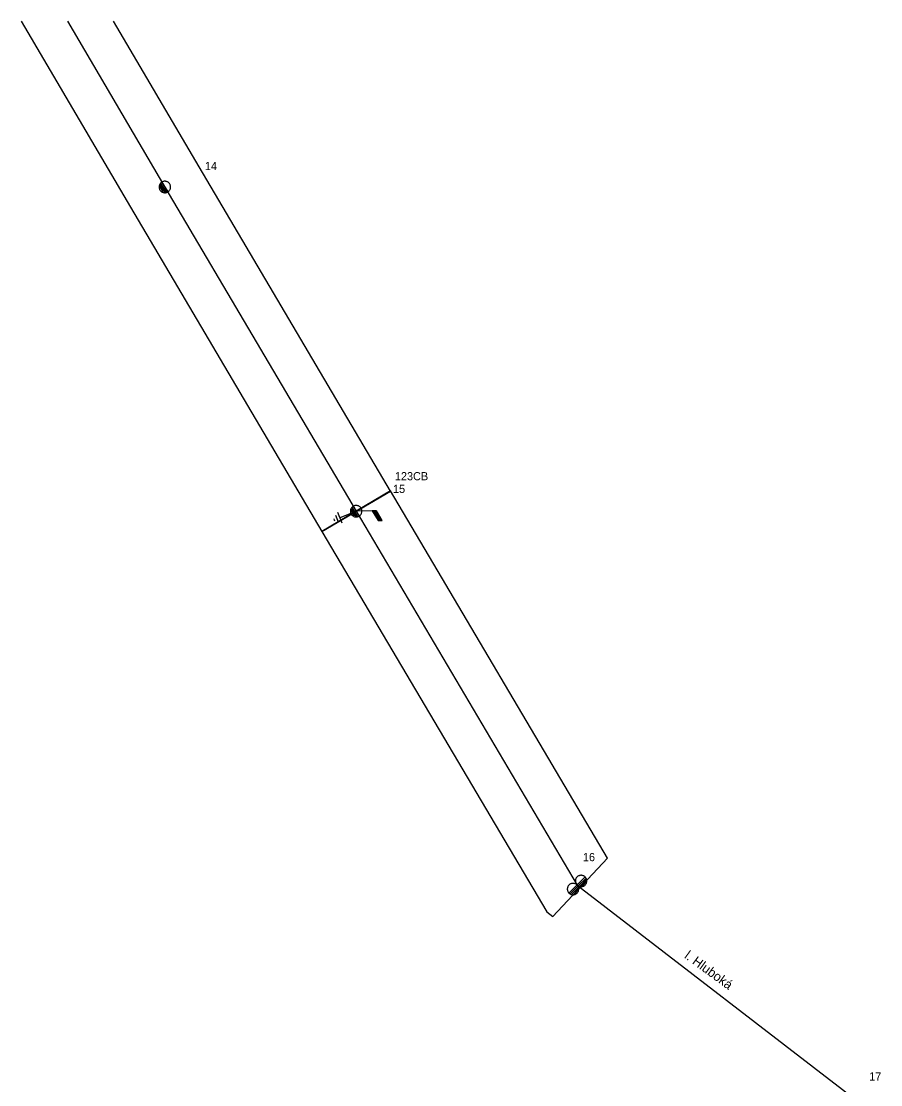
# Model space of a CAD drawing. Extents: x -762500 to -761250, y -1155000 to -1154000.
# Drawn here: x -761851.8 to -761668.3, y -1154227 to -1154000 of the extents above; entities that cross this region are included whole.
import ezdxf

# ---------------------------------------------------------------- set-up
doc = ezdxf.new("R2010")
doc.units = 0
for name, color, linetype in [('Vrstva 1', 7, 'Continuous'), ('Vrstva 11', 7, 'Continuous'), ('Vrstva 12', 7, 'Continuous'), ('Vrstva 13', 7, 'Continuous'), ('Vrstva 14', 7, 'Continuous'), ('Vrstva 15', 7, 'Continuous'), ('Vrstva 3', 7, 'Continuous'), ('Vrstva 35', 7, 'Continuous')]:
    doc.layers.add(name, color=color, linetype=linetype)

msp = doc.modelspace()

# ---------------------------------------------------------------- linework, layer by layer
at = {"layer": 'Vrstva 1'}
for points in [[(-761841.93, -1154000), (-761821.12, -1154035.38), (-761780.27, -1154104.58)], [(-761780.27, -1154104.58), (-761733.11, -1154184.36), (-761670.23, -1154232.75)]]:
    msp.add_lwpolyline(points, dxfattribs=at)
at = {"layer": 'Vrstva 11'}
for p, q in [((-761776.78, -1154104.503), (-761775.538, -1154106.571)), ((-761776.723, -1154104.502), (-761775.48, -1154106.57)), ((-761776.665, -1154104.501), (-761775.422, -1154106.569)), ((-761776.607, -1154104.499), (-761775.365, -1154106.568)), ((-761776.55, -1154104.498), (-761775.307, -1154106.567)), ((-761776.492, -1154104.497), (-761775.249, -1154106.566)), ((-761776.435, -1154104.495), (-761775.192, -1154106.565)), ((-761776.377, -1154104.494), (-761775.134, -1154106.563)), ((-761776.32, -1154104.493), (-761775.076, -1154106.562)), ((-761776.262, -1154104.492), (-761775.018, -1154106.561)), ((-761776.204, -1154104.49), (-761774.961, -1154106.56)), ((-761776.147, -1154104.489), (-761774.903, -1154106.559)), ((-761776.089, -1154104.488), (-761774.845, -1154106.558)), ((-761776.032, -1154104.487), (-761774.787, -1154106.557)), ((-761775.974, -1154104.485), (-761775.762, -1154104.838))]:
    msp.add_line(p, q, dxfattribs=at)
msp.add_lwpolyline([(-761775.973, -1154104.485), (-761780.27, -1154104.58)], dxfattribs=at)
msp.add_lwpolyline([(-761774.734, -1154106.556), (-761775.973, -1154104.485), (-761776.834, -1154104.504), (-761775.591, -1154106.572)], close=True, dxfattribs=at)
at = {"layer": 'Vrstva 13'}
for points in [[(-761820.495, -1154036.427), (-761820.388, -1154036.355), (-761820.29, -1154036.272), (-761820.201, -1154036.18), (-761820.121, -1154036.078), (-761820.053, -1154035.97), (-761819.997, -1154035.854), (-761819.953, -1154035.733), (-761819.922, -1154035.609), (-761819.904, -1154035.481), (-761819.899, -1154035.352), (-761819.908, -1154035.224), (-761819.931, -1154035.098), (-761819.966, -1154034.974), (-761820.014, -1154034.855), (-761820.075, -1154034.741), (-761820.146, -1154034.635), (-761820.229, -1154034.536), (-761820.322, -1154034.447), (-761820.423, -1154034.368), (-761820.532, -1154034.299), (-761820.648, -1154034.243), (-761820.769, -1154034.199), (-761820.894, -1154034.168), (-761821.021, -1154034.15), (-761821.149, -1154034.146), (-761821.277, -1154034.155), (-761821.404, -1154034.177), (-761821.528, -1154034.212), (-761821.647, -1154034.26), (-761821.76, -1154034.321), (-761821.867, -1154034.393), (-761821.965, -1154034.475), (-761822.055, -1154034.568), (-761822.134, -1154034.67), (-761822.202, -1154034.779), (-761822.258, -1154034.894), (-761822.302, -1154035.015), (-761822.334, -1154035.14), (-761822.351, -1154035.267), (-761822.356, -1154035.395), (-761822.347, -1154035.524), (-761822.325, -1154035.65), (-761822.289, -1154035.774), (-761822.241, -1154035.893), (-761822.181, -1154036.006), (-761822.109, -1154036.113), (-761822.026, -1154036.211), (-761821.934, -1154036.301), (-761821.832, -1154036.38), (-761821.724, -1154036.448), (-761821.608, -1154036.505), (-761821.487, -1154036.549), (-761821.362, -1154036.58), (-761821.235, -1154036.597), (-761821.106, -1154036.602), (-761820.978, -1154036.593), (-761820.852, -1154036.571), (-761820.728, -1154036.535), (-761820.609, -1154036.487), (-761820.495, -1154036.427)], [(-761822.18, -1154034.837), (-761821.162, -1154036.532)], [(-761822.022, -1154034.541), (-761820.845, -1154036.499)], [(-761821.756, -1154034.314), (-761820.49, -1154036.42)], [(-761822.288, -1154035.216), (-761821.557, -1154036.433)], [(-761779.645, -1154105.627), (-761779.538, -1154105.555), (-761779.44, -1154105.472), (-761779.351, -1154105.38), (-761779.271, -1154105.278), (-761779.203, -1154105.17), (-761779.147, -1154105.054), (-761779.103, -1154104.933), (-761779.072, -1154104.809), (-761779.054, -1154104.681), (-761779.049, -1154104.552), (-761779.058, -1154104.424), (-761779.081, -1154104.298), (-761779.116, -1154104.174), (-761779.164, -1154104.055), (-761779.225, -1154103.941), (-761779.296, -1154103.835), (-761779.379, -1154103.736), (-761779.472, -1154103.647), (-761779.573, -1154103.568), (-761779.682, -1154103.499), (-761779.798, -1154103.443), (-761779.919, -1154103.399), (-761780.044, -1154103.368), (-761780.171, -1154103.35), (-761780.299, -1154103.346), (-761780.427, -1154103.355), (-761780.554, -1154103.377), (-761780.678, -1154103.412), (-761780.797, -1154103.46), (-761780.91, -1154103.521), (-761781.017, -1154103.593), (-761781.115, -1154103.675), (-761781.205, -1154103.768), (-761781.284, -1154103.87), (-761781.352, -1154103.979), (-761781.408, -1154104.094), (-761781.452, -1154104.215), (-761781.484, -1154104.34), (-761781.501, -1154104.467), (-761781.506, -1154104.595), (-761781.497, -1154104.724), (-761781.475, -1154104.85), (-761781.439, -1154104.974), (-761781.391, -1154105.093), (-761781.331, -1154105.206), (-761781.259, -1154105.313), (-761781.176, -1154105.411), (-761781.084, -1154105.501), (-761780.982, -1154105.58), (-761780.874, -1154105.648), (-761780.758, -1154105.705), (-761780.637, -1154105.749), (-761780.512, -1154105.78), (-761780.385, -1154105.797), (-761780.256, -1154105.802), (-761780.128, -1154105.793), (-761780.002, -1154105.771), (-761779.878, -1154105.735), (-761779.759, -1154105.687), (-761779.645, -1154105.627)], [(-761781.438, -1154104.416), (-761780.707, -1154105.633)], [(-761781.33, -1154104.037), (-761780.312, -1154105.732)], [(-761781.172, -1154103.741), (-761779.995, -1154105.699)], [(-761780.906, -1154103.514), (-761779.64, -1154105.62)], [(-761731.386, -1154182.636), (-761731.481, -1154182.551), (-761731.584, -1154182.476), (-761731.694, -1154182.412), (-761731.811, -1154182.361), (-761731.932, -1154182.321), (-761732.057, -1154182.294), (-761732.184, -1154182.281), (-761732.311, -1154182.281), (-761732.438, -1154182.294), (-761732.563, -1154182.321), (-761732.684, -1154182.361), (-761732.801, -1154182.412), (-761732.912, -1154182.476), (-761733.014, -1154182.551), (-761733.109, -1154182.637), (-761733.195, -1154182.731), (-761733.27, -1154182.834), (-761733.333, -1154182.945), (-761733.385, -1154183.062), (-761733.425, -1154183.183), (-761733.451, -1154183.307), (-761733.465, -1154183.434), (-761733.465, -1154183.561), (-761733.451, -1154183.689), (-761733.425, -1154183.814), (-761733.385, -1154183.935), (-761733.333, -1154184.051), (-761733.27, -1154184.162), (-761733.195, -1154184.265), (-761733.109, -1154184.36), (-761733.014, -1154184.445), (-761732.912, -1154184.52), (-761732.801, -1154184.584), (-761732.684, -1154184.636), (-761732.563, -1154184.675), (-761732.438, -1154184.701), (-761732.311, -1154184.715), (-761732.184, -1154184.715), (-761732.057, -1154184.701), (-761731.932, -1154184.675), (-761731.811, -1154184.635), (-761731.694, -1154184.584), (-761731.584, -1154184.52), (-761731.481, -1154184.445), (-761731.386, -1154184.359), (-761731.3, -1154184.265), (-761731.226, -1154184.162), (-761731.162, -1154184.051), (-761731.11, -1154183.934), (-761731.07, -1154183.813), (-761731.044, -1154183.689), (-761731.031, -1154183.561), (-761731.031, -1154183.434), (-761731.044, -1154183.307), (-761731.071, -1154183.182), (-761731.11, -1154183.061), (-761731.162, -1154182.945), (-761731.226, -1154182.834), (-761731.3, -1154182.731), (-761731.385, -1154182.636)], [(-761733.109, -1154184.359), (-761733.205, -1154184.274), (-761733.307, -1154184.199), (-761733.418, -1154184.136), (-761733.534, -1154184.084), (-761733.656, -1154184.044), (-761733.781, -1154184.018), (-761733.908, -1154184.005), (-761734.035, -1154184.005), (-761734.162, -1154184.018), (-761734.287, -1154184.045), (-761734.408, -1154184.084), (-761734.525, -1154184.136), (-761734.635, -1154184.199), (-761734.738, -1154184.274), (-761734.833, -1154184.36), (-761734.918, -1154184.455), (-761734.993, -1154184.557), (-761735.057, -1154184.668), (-761735.109, -1154184.785), (-761735.149, -1154184.906), (-761735.175, -1154185.031), (-761735.188, -1154185.158), (-761735.188, -1154185.285), (-761735.175, -1154185.412), (-761735.148, -1154185.537), (-761735.109, -1154185.658), (-761735.057, -1154185.775), (-761734.993, -1154185.886), (-761734.918, -1154185.988), (-761734.833, -1154186.083), (-761734.738, -1154186.169), (-761734.635, -1154186.244), (-761734.525, -1154186.307), (-761734.408, -1154186.359), (-761734.286, -1154186.399), (-761734.162, -1154186.425), (-761734.035, -1154186.438), (-761733.908, -1154186.438), (-761733.781, -1154186.425), (-761733.656, -1154186.398), (-761733.534, -1154186.359), (-761733.418, -1154186.307), (-761733.307, -1154186.244), (-761733.205, -1154186.169), (-761733.109, -1154186.083), (-761733.024, -1154185.988), (-761732.949, -1154185.886), (-761732.886, -1154185.775), (-761732.833, -1154185.658), (-761732.794, -1154185.537), (-761732.768, -1154185.412), (-761732.754, -1154185.285), (-761732.754, -1154185.158), (-761732.768, -1154185.031), (-761732.794, -1154184.906), (-761732.834, -1154184.785), (-761732.886, -1154184.668), (-761732.949, -1154184.557), (-761733.024, -1154184.455), (-761733.109, -1154184.36)], [(-761734.833, -1154186.083), (-761731.386, -1154182.636)], [(-761734.589, -1154186.273), (-761732.92, -1154184.604)], [(-761732.865, -1154184.549), (-761731.196, -1154182.88)], [(-761732.553, -1154184.672), (-761731.074, -1154183.192)], [(-761732.159, -1154184.712), (-761731.033, -1154183.586)], [(-761734.277, -1154186.395), (-761732.797, -1154184.916)], [(-761733.883, -1154186.435), (-761732.757, -1154185.309)]]:
    msp.add_lwpolyline(points, dxfattribs=at)
at = {"layer": 'Vrstva 15'}
for points in [[(-761783.274, -1154107.146), (-761784.211, -1154104.828)], [(-761781.425, -1154105.05), (-761783.743, -1154105.987)], [(-761784.902, -1154106.455), (-761784.997, -1154106.218)], [(-761784.802, -1154106.702), (-761784.902, -1154106.455)], [(-761784.03, -1154106.931), (-761784.62, -1154105.471)]]:
    msp.add_lwpolyline(points, dxfattribs=at)
at = {"layer": 'Vrstva 35'}
msp.add_lwpolyline([(-761851.79, -1154000), (-761828.44, -1154039.7), (-761787.59, -1154108.9), (-761772.95, -1154100.26), (-761813.8, -1154031.06), (-761832.06, -1154000)], dxfattribs=at)
msp.add_lwpolyline([(-761726.63, -1154178.62), (-761772.95, -1154100.25), (-761787.59, -1154108.9), (-761739.59, -1154190.1), (-761738.29, -1154191.1)], close=True, dxfattribs=at)

# ---------------------------------------------------------------- texts
at = {"layer": 'Vrstva 12'}
msp.add_text('123CB', height=1.74, dxfattribs=at).set_placement((-761772.01, -1154097.97))
at = {"layer": 'Vrstva 14'}
for s, p in [('14', (-761812.58, -1154031.76)), ('15', (-761772.41, -1154100.68)), ('16', (-761731.86, -1154179.27)), ('17', (-761670.73, -1154226.08))]:
    msp.add_text(s, height=1.74, dxfattribs=at).set_placement(p)
at = {"layer": 'Vrstva 3'}
msp.add_text('l. Hluboká', height=1.9886, rotation=323.98014, dxfattribs=at).set_placement((-761710.34, -1154199.82))

doc.saveas('drawing.dxf')
